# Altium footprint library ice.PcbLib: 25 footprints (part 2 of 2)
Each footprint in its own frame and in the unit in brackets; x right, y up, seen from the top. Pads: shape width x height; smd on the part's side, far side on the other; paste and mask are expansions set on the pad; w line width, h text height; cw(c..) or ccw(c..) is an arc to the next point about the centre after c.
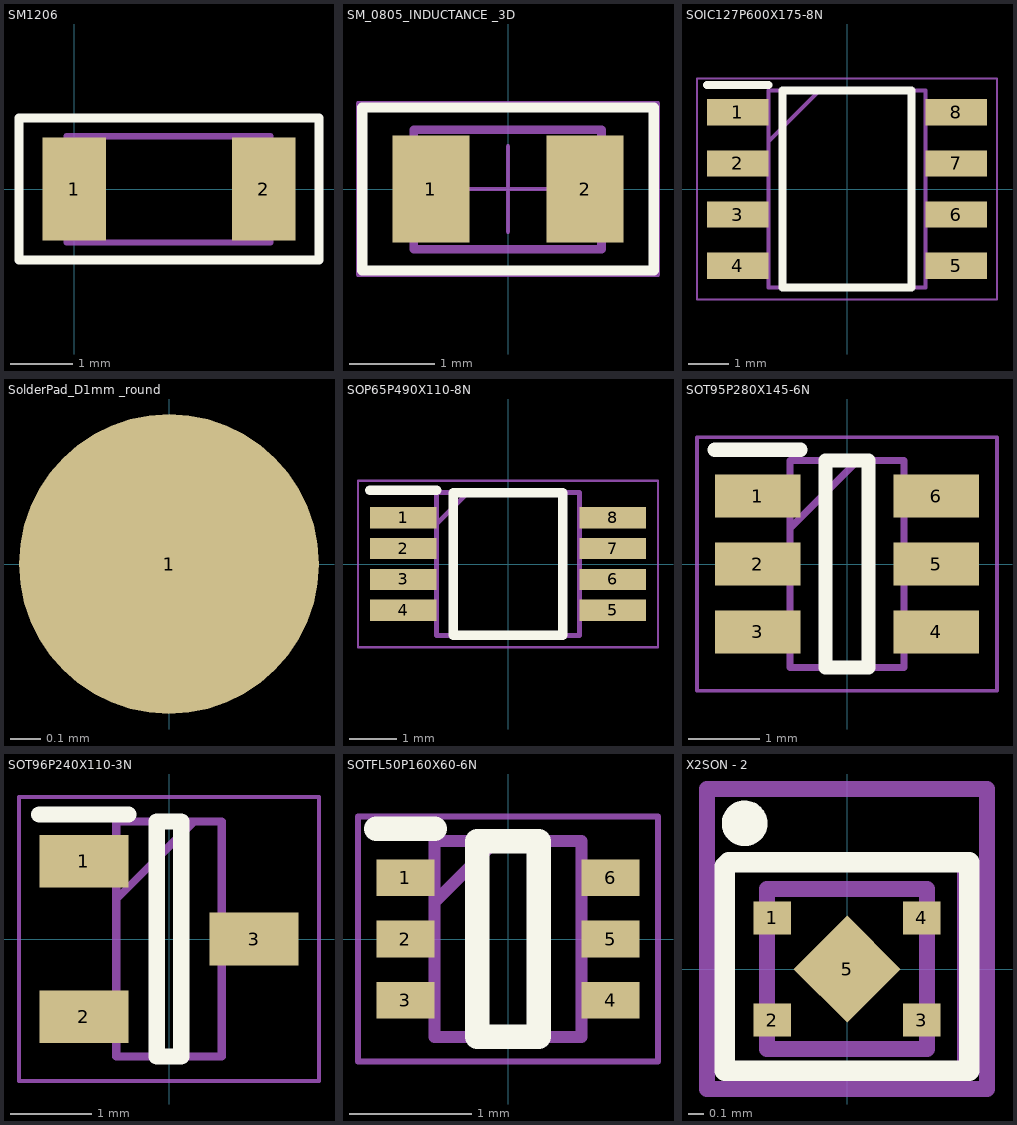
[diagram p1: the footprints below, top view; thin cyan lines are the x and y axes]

## SM1206 [mil]
height 47.24
pads (2):
  rect 40x65 smd: 1(0,0) 2(120,0)
Top Overlay:
  lines w5.91: -35,-45 -35,45 155,45 155,-45 -35,-45
Top Courtyard:
  lines w3.94: -35,-45 155,-45 155,45 -35,45 -35,-45
M13_3D_Outline:
  lines w3.94: -5,-33.9 -5,33.37 124.22,33.37 124.22,-33.9 -5,-33.9
Top Assembly:
  lines w3.94: -35,-45 155,-45 155,45 -35,45 -35,-45
  text ".Designator" at 50.91,-4.91 h27.56
3D body "RES_1206.STEP": height 24.02, standoff 0, extent -4.99,-33.5 125,33.51

## SM_0805_INDUCTANCE _3D [mm] "chip inductanse 0805 inch"
height 1.2
pads (2):
  rect 0.9x1.25 smd: 1(-0.9,0) 2(0.9,0)
Top Overlay:
  lines w0.12: -1.7,-0.95 1.7,-0.95 1.7,0.95 -1.7,0.95 -1.7,-0.95
Top Courtyard:
  lines w0.05: -0.5,0 0.5,0 ; 0,-0.5 0,0.5 ; -1.75,-1 1.75,-1 1.75,1 -1.75,1 -1.75,-1
M13_3D_Outline:
  lines w0.1: -1.102,-0.703 1.091,-0.703 1.091,0.691 -1.102,0.691 -1.102,-0.703
Mechanical 14:
  lines w0.1: -1.7,-0.95 1.7,-0.95 1.7,0.95 -1.7,0.95 -1.7,-0.95
Top Assembly:
  lines w0.05: -0.5,0 0.5,0 ; 0,-0.5 0,0.5 ; -1.75,-1 1.75,-1 1.75,1 -1.75,1 -1.75,-1
  text ".Designator" at -0.104,0.002 h0.7
3D body "INDC2012X110N.stp": height 1.1, standoff 0, extent -1.1,-0.7 1.1,0.7

## SOIC127P600X175-8N [mm]
height 1.2
pads (8):
  rect 1.525x0.65 smd: 1(-2.712,1.905) 2(-2.712,0.635) 3(-2.712,-0.635) 4(-2.712,-1.905) 5(2.712,-1.905) 6(2.712,-0.635) 7(2.712,0.635) 8(2.712,1.905)
Top Overlay:
  lines w0.2: -3.475,2.58 -1.95,2.58 ; -1.6,-2.45 -1.6,2.45 1.6,2.45 1.6,-2.45 -1.6,-2.45
Top Courtyard:
  lines w0.05: -3.725,-2.75 3.725,-2.75 3.725,2.75 -3.725,2.75 -3.725,-2.75
M13_3D_Outline:
  lines w0.1: -1.95,1.18 -0.68,2.45 ; -1.95,-2.45 -1.95,2.45 1.95,2.45 1.95,-2.45 -1.95,-2.45
Top Assembly:
  lines w0.05: -3.725,-2.75 -3.725,2.75 3.725,2.75 3.725,-2.75 -3.725,-2.75
  text ".Designator" at -0.104,0.002 h0.7
3D body "NE555DR.stp": height 1.75, standoff 0, extent -3,-2.45 3,2.45

## SolderPad_D1mm _round [mm] "7mm solder circle for finger touch"
pads (1):
  round 1 smd: 1(0,0)

## SOP65P490X110-8N [mm]
height 1.2
pads (8):
  rect 1.4x0.45 smd: 1(-2.2,0.975) 2(-2.2,0.325) 3(-2.2,-0.325) 4(-2.2,-0.975) 5(2.2,-0.975) 6(2.2,-0.325) 7(2.2,0.325) 8(2.2,0.975)
Top Overlay:
  lines w0.2: -2.9,1.55 -1.5,1.55 ; -1.15,-1.5 1.15,-1.5 1.15,1.5 -1.15,1.5 -1.15,-1.5
Top Courtyard:
  lines w0.05: -3.15,-1.75 3.15,-1.75 3.15,1.75 -3.15,1.75 -3.15,-1.75
M13_3D_Outline:
  lines w0.1: -1.5,0.85 -0.85,1.5 ; -1.5,-1.5 1.5,-1.5 1.5,1.5 -1.5,1.5 -1.5,-1.5
Top Assembly:
  lines w0.05: -3.15,-1.75 3.15,-1.75 3.15,1.75 -3.15,1.75 -3.15,-1.75
  text ".Designator" at -0.104,0.002 h0.7
3D body "MCP4812-E_MS.stp": height 1.1, standoff 0, extent -2.45,-1.5 2.45,1.5

## SOT95P280X145-6N [mm]
height 1.2
pads (6):
  rect 1.2x0.6 smd: 1(-1.25,0.95) 2(-1.25,0) 3(-1.25,-0.95) 4(1.25,-0.95) 5(1.25,0) 6(1.25,0.95)
Top Overlay:
  lines w0.2: -1.85,1.6 -0.65,1.6 ; -0.3,-1.45 -0.3,1.45 0.3,1.45 0.3,-1.45 -0.3,-1.45
M13_3D_Outline:
  lines w0.1: -0.8,0.5 0.15,1.45 ; -0.8,-1.45 -0.8,1.45 0.8,1.45 0.8,-1.45 -0.8,-1.45
Top Assembly:
  lines w0.05: -2.1,-1.775 -2.1,1.775 ; -2.1,-1.775 2.1,-1.775 ; -2.1,-1.775 -2.1,1.775 ; -2.1,-1.775 2.1,-1.775 ; -2.1,1.775 2.1,1.775 ; -2.1,1.775 2.1,1.775 ; 2.1,-1.775 2.1,1.775 ; 2.1,-1.775 2.1,1.775
  text ".Designator" at -0.104,0.002 h0.7
3D body "SN74LVC2G17DBVR.stp": height 1.45, standoff 0, extent -1.4,-1.45 1.4,1.45

## SOT96P240X110-3N [mm]
height 1.2
pads (3):
  rect 1.1x0.65 smd: 1(-1.05,0.96) 2(-1.05,-0.96) 3(1.05,0)
Top Overlay:
  lines w0.2: -1.6,1.535 -0.5,1.535 ; -0.15,-1.45 -0.15,1.45 0.15,1.45 0.15,-1.45 -0.15,-1.45
Top Courtyard:
  lines w0.05: -1.85,-1.75 1.85,-1.75 1.85,1.75 -1.85,1.75 -1.85,-1.75
M13_3D_Outline:
  lines w0.1: -0.65,0.49 0.31,1.45 ; -0.65,-1.45 -0.65,1.45 0.65,1.45 0.65,-1.45 -0.65,-1.45
Top Assembly:
  lines w0.05: -1.85,-1.75 -1.85,1.75 1.85,1.75 1.85,-1.75 -1.85,-1.75
  text ".Designator" at -0.104,0.002 h0.7
3D body "MMBD7000HS-7-F.stp": height 1.1, standoff 0, extent -1.2,-1.45 1.2,1.45

## SOTFL50P160X60-6N [mm]
height 1.2
pads (6):
  rect 0.475x0.3 smd: 1(-0.838,0.5) 2(-0.838,0) 3(-0.838,-0.5) 4(0.838,-0.5) 5(0.838,0) 6(0.838,0.5)
Top Overlay:
  lines w0.2: -1.075,0.9 -0.6,0.9 ; -0.25,-0.8 -0.25,0.8 0.25,0.8 0.25,-0.8 -0.25,-0.8
Top Courtyard:
  lines w0.05: -1.225,-1 -1.225,1 1.225,1 1.225,-1 -1.225,-1
M13_3D_Outline:
  lines w0.1: -0.6,0.3 -0.1,0.8 ; -0.6,-0.8 -0.6,0.8 0.6,0.8 0.6,-0.8 -0.6,-0.8
Top Assembly:
  lines w0.05: -1.225,-1 -1.225,1 1.225,1 1.225,-1 -1.225,-1
  text ".Designator" at -0.104,-0.125 h0.7
3D body "TMP112AIDRLR.stp": height 0.6, standoff 0, extent -0.8,-0.8 0.8,0.8

## X2SON - 2 [mm] "DQN, X2SON"
height 0.4
pads (5):
  rect 0.24x0.21 smd paste+0 mask+0.08: 1(-0.475,0.325) 2(-0.475,-0.325) 3(0.475,-0.325) 4(0.475,0.325)
  rect 0.48x0.48 smd rot 45 mask+0.075: 5(0,0)
Top Overlay:
  lines w0.13: -0.775,-0.646 -0.775,0.654 -0.75,0.679 0.775,0.679 0.775,-0.621 ; -0.75,-0.646 0.775,-0.646
  lines w0.15: -0.635,0.857 cw(c-0.65,0.925) -0.626,0.859
Top Courtyard:
  lines w0.1: -0.889,-0.762 -0.889,1.143 0.889,1.143 0.889,-0.762 -0.889,-0.762
M13_3D_Outline:
  lines w0.1: -0.508,-0.508 -0.508,0.508 0.508,0.508 0.508,-0.508 -0.508,-0.508
Top Assembly:
  lines w0.05: -0.75,-0.621 0.725,-0.621 0.725,0.679 -0.75,0.679 -0.75,-0.621
  text ".Designator" at -0.104,-0.125 h0.7
3D body "DQN0004A.stp": height 0.37, standoff 0.01, extent -0.5,-0.5 0.5,0.5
